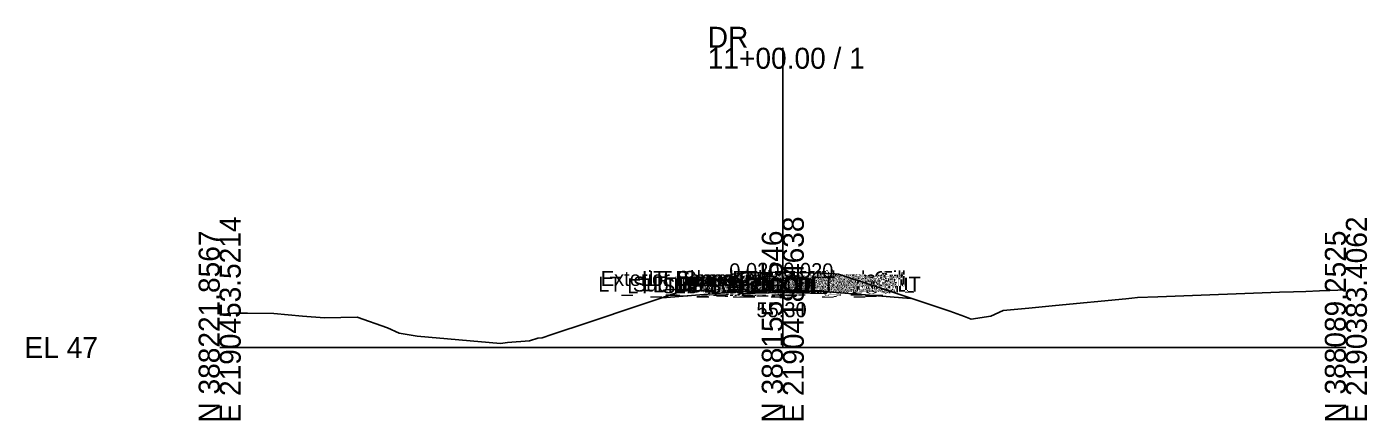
# Model space of a CAD drawing. Extents: x -26 to 153, y 490 to 1524.
# Drawn here: x -25.7 to 152.8, y 990.3 to 1042.8 of the extents above; entities that cross this region are included whole.
import ezdxf

# ---------------------------------------------------------------- set-up
doc = ezdxf.new("R2010")
doc.units = 0
for name, color, linetype in [('Default', 7, 'Continuous'), ('Exist CMT Ground Line', 7, 'Continuous'), ('Exist Cross Section Cell', 7, 'Continuous'), ('Exist XS Center Line Elevation Label', 7, 'Continuous'), ('Prop CMT Pvmt Course 1', 7, 'Continuous'), ('Prop CMT Pvmt Course 2', 7, 'Continuous'), ('Prop CMT Pvmt Surface', 7, 'Continuous'), ('Prop CMT Shld Paved Course 1', 7, 'Continuous'), ('Prop CMT Shld Paved Course 2', 7, 'Continuous'), ('Prop CMT Slope Grass', 7, 'Continuous'), ('Prop CMT Subgrade Earthwork', 7, 'Continuous'), ('Prop XS SE Text', 7, 'Continuous'), ('Scratch_Level_1', 7, 'Continuous')]:
    doc.layers.add(name, color=color, linetype=linetype)

msp = doc.modelspace()

# ---------------------------------------------------------------- linework, layer by layer
at = {"layer": 'Exist CMT Ground Line'}
for p, q in [((62.32, 1007.79), (68.35, 1009.8)), ((68.35, 1009.8), (69.35, 1009.88)), ((69.35, 1009.88), (69.86, 1009.92)), ((69.86, 1009.92), (70.35, 1009.96)), ((70.35, 1009.96), (71.93, 1009.99)), ((71.93, 1009.99), (75, 1010.05)), ((75, 1010.05), (75, 1010.05)), ((75, 1010.05), (78.58, 1009.98)), ((78.58, 1009.98), (80.42, 1009.94)), ((80.42, 1009.94), (80.91, 1009.9)), ((80.91, 1009.9), (81.91, 1009.82)), ((81.91, 1009.82), (82.42, 1009.78)), ((82.42, 1009.78), (87.25, 1008.17)), ((49.22, 1003.37), (62.32, 1007.79)), ((87.25, 1008.17), (97.25, 1004.84)), ((128.4, 1006.89), (138.86, 1007.28)), ((138.86, 1007.28), (141.16, 1007.37)), ((141.16, 1007.37), (143.04, 1007.44)), ((143.04, 1007.44), (144.67, 1007.5)), ((144.67, 1007.5), (146.49, 1007.57)), ((146.49, 1007.57), (147.86, 1007.62)), ((147.86, 1007.62), (150, 1007.68)), ((104.37, 1004.95), (107.76, 1005.27)), ((107.76, 1005.27), (111.31, 1005.61)), ((111.31, 1005.61), (120.7, 1006.52)), ((120.7, 1006.52), (121.51, 1006.59)), ((121.51, 1006.59), (122.23, 1006.66)), ((122.23, 1006.66), (124.96, 1006.77)), ((124.96, 1006.77), (128.4, 1006.89)), ((0, 1004.42), (1.85, 1004.59)), ((1.85, 1004.59), (3.71, 1004.61)), ((3.71, 1004.61), (7.21, 1004.54)), ((7.21, 1004.54), (11.02, 1004.19)), ((11.02, 1004.19), (13.96, 1003.98)), ((13.96, 1003.98), (18.29, 1004.07)), ((18.29, 1004.07), (22.34, 1002.65)), ((44.24, 1001.76), (49.22, 1003.37)), ((97.25, 1004.84), (99.19, 1004.13)), ((99.19, 1004.13), (100.11, 1003.8)), ((100.11, 1003.8), (102.7, 1004.2)), ((102.7, 1004.2), (104.37, 1004.95)), ((22.34, 1002.65), (23.91, 1001.94)), ((23.91, 1001.94), (26.3, 1001.53)), ((42.93, 1001.28), (44.24, 1001.76)), ((26.3, 1001.53), (37.41, 1000.53)), ((37.41, 1000.53), (38.35, 1000.68)), ((38.35, 1000.68), (41.26, 1000.9)), ((41.26, 1000.9), (42.37, 1001.24)), ((42.37, 1001.24), (42.93, 1001.28))]:
    msp.add_line(p, q, dxfattribs=at)
at = {"layer": 'Exist Cross Section Cell'}
for p, q in [((75, 1000), (75, 1039.99)), ((0, 1000), (75, 1000)), ((75, 1000), (150, 1000))]:
    msp.add_line(p, q, dxfattribs=at)
at = {"layer": 'Prop CMT Pvmt Course 1'}
for points in [[(75, 1007.6), (69.5, 1007.49)], [(69.5, 1007.48), (75, 1007.59)], [(69.5, 1007.49), (69.5, 1007.48)], [(75, 1007.59), (75, 1007.6)], [(75, 1007.6), (80.5, 1007.49)], [(75, 1007.59), (75, 1007.6)], [(80.5, 1007.48), (75, 1007.59)], [(80.5, 1007.49), (80.5, 1007.48)]]:
    msp.add_lwpolyline(points, dxfattribs=at)
msp.add_lwpolyline([(75, 1007.59), (75, 1007.47), (75, 1007.47), (75, 1007.59)], close=True, dxfattribs=at)
msp.add_lwpolyline([(75, 1007.59), (75, 1007.47), (75, 1007.47), (75, 1007.59)], close=True, dxfattribs=at)
at = {"layer": 'Prop CMT Pvmt Course 2'}
for points in [[(75, 1007.59), (69.5, 1007.48)], [(69.5, 1007.48), (69.5, 1007.23)], [(69.5, 1007.23), (75, 1007.34)], [(75, 1007.34), (75, 1007.59)], [(75, 1007.34), (75, 1007.59)], [(75, 1007.59), (80.5, 1007.48)], [(80.5, 1007.23), (75, 1007.34)], [(80.5, 1007.48), (80.5, 1007.23)]]:
    msp.add_lwpolyline(points, dxfattribs=at)
at = {"layer": 'Prop CMT Pvmt Surface'}
for points in [[(75, 1007.6), (69.5, 1007.49)], [(75, 1007.6), (80.5, 1007.49)]]:
    msp.add_lwpolyline(points, dxfattribs=at)
at = {"layer": 'Prop CMT Shld Paved Course 1'}
for points in [[(69.5, 1007.49), (69.49, 1007.48)], [(69.49, 1007.48), (69.5, 1007.48)], [(69.5, 1007.48), (69.5, 1007.49)], [(80.5, 1007.49), (80.51, 1007.48)], [(80.5, 1007.48), (80.5, 1007.49)], [(80.51, 1007.48), (80.5, 1007.48)]]:
    msp.add_lwpolyline(points, dxfattribs=at)
at = {"layer": 'Prop CMT Shld Paved Course 2'}
for points in [[(69.5, 1007.48), (69.49, 1007.48), (69.49, 1007.48), (69.23, 1007.22)], [(69.23, 1007.22), (69.5, 1007.23)], [(69.5, 1007.23), (69.5, 1007.48)], [(80.5, 1007.48), (80.51, 1007.48), (80.51, 1007.48), (80.77, 1007.22)], [(80.5, 1007.23), (80.5, 1007.48)], [(80.77, 1007.22), (80.5, 1007.23)]]:
    msp.add_lwpolyline(points, dxfattribs=at)
at = {"layer": 'Prop CMT Slope Grass'}
for points in [[(69.5, 1007.49), (58.93, 1006.64)], [(80.5, 1007.49), (92.07, 1006.56)]]:
    msp.add_lwpolyline(points, dxfattribs=at)
at = {"layer": 'Prop CMT Subgrade Earthwork'}
for points in [[(69.5, 1007.23), (69.23, 1007.22), (69.01, 1007.45)], [(75, 1007.34), (69.5, 1007.23)], [(75, 1007.34), (80.5, 1007.23)], [(80.5, 1007.23), (80.77, 1007.22), (80.99, 1007.45)]]:
    msp.add_lwpolyline(points, dxfattribs=at)

# ---------------------------------------------------------------- texts
at = {"layer": 'Default'}
msp.add_text('-', height=0.0001, dxfattribs=at).set_placement((0, 1000))
at = {"layer": 'Exist Cross Section Cell'}
for s, p in [('DR', (65, 1039.99)), ('11+00.00 / 1', (65, 1037.19)), ('EL 47', (-26, 998.6))]:
    msp.add_text(s, height=2.8, dxfattribs=at).set_placement(p)
for s, p in [('E 2190453.5214', (2.8, 990)), ('E 2190418.4638', (77.8, 990)), ('E 2190383.4062', (152.8, 990)), ('N 388221.8567', (0, 990)), ('N 388155.5546', (75, 990)), ('N 388089.2525', (150, 990))]:
    msp.add_text(s, height=2.8, rotation=90, dxfattribs=at).set_placement(p)
at = {"layer": 'Exist XS Center Line Elevation Label'}
msp.add_text('55.30', height=2, dxfattribs=at).set_placement((71.49, 1004.05))
at = {"layer": 'Prop XS SE Text'}
for rotation, p in [(1.1458, (67.89, 1009.22)), (358.8542, (75.02, 1009.35))]:
    msp.add_text('0.020', height=2, rotation=rotation, dxfattribs=at).set_placement(p)
at = {"layer": 'Scratch_Level_1'}
for s, p in [('LT_Sub_Trench_Out_DLT', (50.42, 1007.47)), ('Exterior Boundary', (50.75, 1008.22)), ('LT_Sub_Trench_Out', (54.29, 1007.24)), ('LT_Slope_Cut', (56.25, 1008.22)), ('LT_PS2_Shelf_Out', (56.32, 1007.5)), ('LT_Slope_Fill', (57.13, 1008.22)), ('LT_GS_OS_CTL', (57.72, 1007.35)), ('LT_Sub_OEOT', (60.43, 1007.25)), ('LT_PV2_OEOT', (60.52, 1007.5)), ('LT_PS2_OEOP', (60.58, 1007.5)), ('LT_PV1_OEOT', (61.09, 1007.51)), ('RT_Sub_Trench_Out_DLT', (61.43, 1007.45)), ('RT_Sub_OEEOP', (64.17, 1007.34)), ('LT_Sub_OEEOP', (64.21, 1007.34)), ('RT_PV2_OEEOP', (64.26, 1007.59)), ('LT_PV2_OEEOP', (64.31, 1007.59)), ('RT_PV1_OEEOP', (64.83, 1007.47)), ('RT_Sub_Trench_Out', (64.84, 1007.23)), ('LT_PV1_OEEOP', (64.87, 1007.47)), ('RT_PV2_IEEOP', (64.91, 1007.59)), ('LT_PV2_IEEOP', (64.95, 1007.59)), ('RT_PV1_IEEOP', (65.47, 1007.47)), ('LT_PV1_IEEOP', (65.52, 1007.47)), ('RT_PS2_Shelf_Out', (66.37, 1007.48)), ('Exterior Boundary', (68.3, 1008.2)), ('PV2_PGL', (68.91, 1007.59)), ('PV1_PGL', (69.47, 1007.6)), ('RT_Sub_OEOT', (70.45, 1007.23)), ('RT_PV2_OEOT', (70.55, 1007.48)), ('RT_PS2_OEOP', (70.62, 1007.48)), ('RT_PV1_OEOT', (71.11, 1007.49)), ('RT_GS_OS_CTL', (71.74, 1007.33)), ('RT_Slope_Cut', (73.75, 1008.2)), ('RT_Slope_Fill', (74.63, 1008.2))]:
    msp.add_text(s, height=2, dxfattribs=at).set_placement(p)

doc.saveas('drawing.dxf')
